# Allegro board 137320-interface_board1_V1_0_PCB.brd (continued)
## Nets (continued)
N2333053: C28.2 L5.1 U5.6(SW)
N2333454: D8.3 U5.3(EN/UVLO) U5.4(VIN)
N2334537: D6.1(ATHODE) R13.2
N2343328: J4.34
N2348416: D13.3 R32.2 R35.2 U6.14(PA0/ADC1_IN1)
N2348424: D14.3 R30.2 R31.2 U6.11(PC3/ADC12_IN9)
N2355333: Q1.1(GATE) R42.1 U6.57(PB5)
N2356046: Q2.1(GATE) R43.1 U6.58(PB6/I2C1_SCL/UART1_TX)
N2358793: J8.2(B1) R48.1 U8.6(AIN3/REFN1)
N2358897: C50.1 FB4.2 U8.12(AVDD)
N2359035: C47.1 C48.2 R50.2 U8.9(REFP0)
N2359039: C48.1 C49.1 R52.2 U8.8(REFN0)
N2359131: J8.1(A1) R47.1 R50.1 R51.1
N2359257: C42.1 C43.2 R47.2 U8.11(AIN0/REFP1)
N2359261: C43.1 C46.1 R48.2 U8.10(AIN1)
N2361697: C53.1 C54.1 FB5.2 U9.10(AVIN) U9.11(PVIN1) U9.12(PVIN2) U9.13(EN)
N2361859: C55.1 U9.9(SS/TR)
N2361891: L6.1 U9.1(SW1) U9.2(SW2) U9.3(SW3)
N2362117: R53.1 U9.4(PG)
N2363053: C56.2 D18.1 L7.1 U10.3(SW)
N2363081: C56.1 U10.2(BOOST)
N2363123: R56.2 R58.1 U10.8(FB)
N2363179: R57.1 U10.10(RT)
N2363207: C58.1 R55.2
N2363211: R55.1 U10.9(VC)
N2363241: C57.1 FB6.2 R54.1 U10.4(VIN)
N2363393: C59.2 R54.2 U10.5(RUN/SS)
N2364151: J1.43
N2365789: R151.1 U43.5(OC2_N) U43.8(OC1_N)
N2365809: R152.1 R153.2 U43.3(EN1_N) U43.4(EN2_N)
N2368555: R154.1 U45.5(OC2_N) U45.8(OC1_N)
N2368583: R155.1 R156.2 U45.3(EN1_N) U45.4(EN2_N)
N2372492: C194.2 U41.4(C1-)
N2372496: C194.1 U41.2(C1+)
N2372506: C197.1 U41.3(V+)
N2372514: C196.1 U41.7(V-)
N2372518: C195.2 U41.6(C2-)
N2372530: C195.1 U41.5(C2+)
N2372534: R143.2 U41.12(FORCEON)
N2372542: R144.2 U41.16(F\O\R\C\E\O\F\F\)
N2372558: R146.1 U41.1(E\N\)
N2372642: R145.2 U41.9(R_OUT)
N2373113: C199.2 U42.4(C1-)
N2373117: C199.1 U42.2(C1+)
N2373127: C202.1 U42.3(V+)
N2373135: C201.1 U42.7(V-)
N2373139: C200.2 U42.6(C2-)
N2373151: C200.1 U42.5(C2+)
N2373155: R148.2 U42.12(FORCEON)
N2373163: R147.2 U42.16(F\O\R\C\E\O\F\F\)
N2373179: R150.1 U42.1(E\N\)
N2373263: R149.2 U42.9(R_OUT)
N2407837: R123.2 U33.4(RXD)
N2407841: R125.1 U33.5(/RE)
N2408507: R126.2 U34.4(RXD)
N2408511: R127.1 U34.5(/RE)
N2410769: R128.2 U35.4(RXD)
N2410773: R130.1 U35.5(/RE)
N2411439: R131.2 U36.4(RXD)
N2411443: R132.1 U36.5(/RE)
N2413701: R133.2 U37.4(RXD)
N2413705: R135.1 U37.5(/RE)
N2414371: R136.2 U38.4(RXD)
N2414375: R137.1 U38.5(/RE)
N2416633: R138.2 U39.4(RXD)
N2416637: R140.1 U39.5(/RE)
N2417303: R141.2 U40.4(RXD)
N2417307: R142.1 U40.5(/RE)
N2487119: R175.1 R208.1 U49.12(A) U50.12(A)
N2487163: R210.1 U49.10(Z) U50.10(Z)
N2487167: R175.2 R209.1 U49.11(B) U50.11(B)
N2487191: R211.1 U49.9(Y) U50.9(Y)
N2496895: C217.2 U51.4(C1-)
N2496899: C217.1 U51.2(C1+)
N2496903: C215.1 U51.7(V-)
N2496907: C219.1 U51.3(V+)
N2496915: Q4.3(DRAIN) Q6.3(DRAIN) R188.1 U51.11(T_IN)
N2496923: C218.2 U51.6(C2-)
N2496931: C218.1 U51.5(C2+)
N2496939: R178.2 U51.12(FORCEON)
N2496947: R179.2 U51.16(F\O\R\C\E\O\F\F\)
N2496959: R177.1 U51.1(E\N\)
N2497023: R180.2 U51.9(R_OUT)
N2498167: R180.1 R185.2 R186.2
N2498410: Q3.3(DRAIN) Q4.1(GATE) R187.1
N2499294: Q5.3(DRAIN) Q6.1(GATE) R189.1
N2500054: R193.1 U51.13(T_OUT)
N2500096: R194.1 U51.8(R_IN)
N2500172: Q7.3(DRAIN) Q8.1(GATE) R195.1
N2500268: Q9.3(DRAIN) Q10.1(GATE) R197.1
N2500326: Q8.3(DRAIN) Q10.3(DRAIN) R196.1 U52.11(T_IN)
N2500498: R200.1 U52.13(T_OUT)
N2500522: R201.1 U52.8(R_IN)
N2500778: C222.2 U52.4(C1-)
N2500782: C224.1 U52.3(V+)
N2500790: C220.1 U52.7(V-)
N2500794: C222.1 U52.2(C1+)
N2500802: C223.2 U52.6(C2-)
N2500814: R203.2 U52.12(FORCEON)
N2500826: C223.1 U52.5(C2+)
N2500830: R202.1 U52.1(E\N\)
N2500842: R204.2 U52.16(F\O\R\C\E\O\F\F\)
N2500874: R205.2 U52.9(R_OUT)
N2500938: R205.1 R206.2 R207.2
N21751111: D15.1(ATHODE) R41.2
N21777191: R61.2 U11.2(R)
N21777192: R59.1 U11.3(RE_N)
N23783590: R63.1 U12.3(RE_N)
N23783591: R64.2 U12.2(RO)
N23815910: R44.1 U7.3(RE_N)
N23815911: R46.2 U7.2(RO)
N23839151: R68.2 U13.2(R)
N23839152: R65.1 U13.3(RE_N)
N23839610: R69.1 U14.3(RE_N)
N23840811: R70.2 U14.2(RO)
N23858251: R74.2 U15.2(R)
N23858252: R71.1 U15.3(RE_N)
N23858410: R75.1 U16.3(RE_N)
N23859371: R76.2 U16.2(RO)
N23877351: R79.2 U17.2(R)
N23877352: R77.1 U17.3(RE_N)
N23877510: R81.1 U18.3(RE_N)
N23878471: R82.2 U18.2(RO)
N23893201: R84.2 U19.2(R)
N23893202: R83.1 U19.3(RE_N)
N23893360: R87.1 U20.3(RE_N)
N23894321: R88.2 U20.2(RO)
N23909051: R90.2 U21.2(R)
N23909052: R89.1 U21.3(RE_N)
N23909210: R93.1 U22.3(RE_N)
N23910171: R94.2 U22.2(RO)
N23924901: R98.2 U23.2(R)
N23924902: R95.1 U23.3(RE_N)
N23925060: R99.1 U24.3(RE_N)
N23926021: R100.2 U24.2(RO)
N23940751: R104.2 U25.2(R)
N23940752: R101.1 U25.3(RE_N)
N23940910: R105.1 U26.3(RE_N)
N23941871: R106.2 U26.2(RO)
N23956601: R108.2 U27.2(R)
N23956602: R107.1 U27.3(RE_N)
N23956760: R111.1 U28.3(RE_N)
N23957721: R112.2 U28.2(RO)
N24852551: R169.2 U47.2(R)
N24852552: R167.1 U47.3(RE_N)
N24852710: R166.1 U48.3(RE_N)
N24853671: R168.2 U48.2(RO)
N24867031: R174.2 U49.2(R)
N24867032: R172.1 U49.3(RE_N)
N24867190: R171.1 U50.3(RE_N)
N24868151: R173.2 U50.2(RO)

Pads without a net: H1 1; H2 1; H3 1; H4 1; H5 1; H6 1; J1 22 63 64; J2 11 26 45 46; J9 3; NOREF#7 1; NOREF#11 1; NOREF#16 1; NOREF#18 1; NOREF#19 1; NOREF#20 1; SP1 1; SP2 1; SP3 1; SP4 1; SP5 1; SP6 1; SP7 1; SP8 1; U1 10; U3 7; U4 7; U5 9; U6 2 4 16 17 24 29 30 34 35 37 38 39 41 44 45 54 59 61 62; U7 1 8; U8 7 14; U10 7; U11 1 8; U12 1 8; U13 1 8; U14 1 8; U15 1 8; U16 1 8; U17 1 8; U18 1 8; U19 1 8; U20 1 8; U21 1 8; U22 1 8; U23 1 8; U24 1 8; U25 1 8; U26 1 8; U27 1 8; U28 1 8; U41 10; U42 10; U44 4 6; U46 4 6; U47 1 8; U48 1 8; U49 1 8; U50 1 8; U51 10; U52 10

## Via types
v1: diameter 0.559, hole 0.254, TOP to BOTTOM, 1085 vias

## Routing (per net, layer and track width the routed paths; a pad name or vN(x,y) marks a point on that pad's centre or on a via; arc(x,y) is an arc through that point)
GND: length 443.2
  TOP w0.254: U6.63 76.76,48.82 v1(77.09,49.15) ; v1(83.44,37.97) 83.26,37.79 U6.31 ; v1(73.03,40.01) 73.43,40.41 U6.12 ; U41.14 83.99,63.21 v1(84.33,62.87) ; v1(76.96,37.97) 76.76,37.77 U6.18 ; U52.14 102.53,53.43 v1(102.87,53.09) ; U51.14 102.53,37.55 v1(102.87,37.21) ; v1(72.52,46.48) 72.52,45.47 73.07,44.91 U6.3 75.74,44.91 v1(75.82,44.83) ; U42.14 v1(89.19,20.07) ; U6.47 86.94,45.41 v1(87.12,45.59)
  TOP w0.305: U8.4 62.16,20.01 v1(61.85,20.32) 62.19,20.66 U8.3 ; U8.5 62.16,19.36 v1(61.85,19.05)
  TOP w0.381: U19.6 v1(44.45,25.65) ; D24.3 v1(18.03,45.09) ; SW1.4 v1(86.36,25.85) ; C50.2 v1(75.31,19.3) ; C215.2 v1(106.05,28.45) ; C224.2 v1(102.23,44.32) ; v1(102.36,66.42) 102.62,66.67 C27.2 ; Q10.2 v1(109.54,51.18) ; C94.2 v1(48.26,21.08) ; U7.6 v1(139.7,9.91) ; v1(48.26,52.83) C70.2 C69.2 ; v1(119.38,21.08) C213.2 C211.2 ; v1(36.83,9.78) 36.83,9.4 37.47,8.76 R103.2 ; U47.7 v1(116.2,12.83) ; U36.10 v1(124.33,66.67) ; v1(121.16,27.94) 120.78,27.56 C129.2 118.36,27.56 v1(117.98,27.94) ; U25.6 v1(44.45,9.78) ; C162.2 C164.2 v1(117.98,47.62) ; R43.2 v1(79.38,53.21) 79.31,53.27 Q2.2 ; U39.3 v1(124.33,60.96) ; U36.1 v1(124.33,78.11) ; R146.2 v1(72.26,64.77) ; U13.7 v1(45.72,41.53) ; R42.2 v1(80.64,53.21) ; C178.2 C180.2 v1(117.98,62.23) ; U37.3 v1(124.33,46.35) ; J9.6 v1(80.01,76.33) ; v1(81.92,53.21) 81.92,54.13 Q1.2 ; D19.3 v1(18.03,57.78) ; Q6.2 v1(109.54,35.31) ; v1(81.66,31.24) R160.2 R158.2 ; v1(121.16,57.15) 120.78,56.77 118.36,56.77 v1(117.98,57.15) ; C49.2 v1(65.41,12.32) ; D51.3 v1(143.51,39.37) ; C207.2 C209.2 v1(108.58,21.08) ; U36.3 v1(124.33,75.56) ; U11.7 v1(35.56,41.53) ; C155.2 v1(117.98,67.94) ; 122.79,48.9 v1(124.33,48.9) ; R177.2 v1(100.97,28.45) ; v1(72.52,42.93) C31.2 v1(71.12,42.29) v1(69.22,42.29) 67.69,42.29 67.31,42.67 v1(67.31,43.56) v1(67.31,45.85) 67.31,46.74 67.69,47.12 v1(69.22,47.12) v1(71.12,47.12) C30.2 v1(72.52,46.48) ; C55.2 v1(88.52,37.47) ; U21.6 v1(54.61,25.65) ; R19.2 104.9,69.22 v1(105.54,68.58) ; U15.7 v1(55.88,41.53) ; C132.2 C130.2 v1(117.98,33.02) ; v1(36.83,25.65) 36.83,25.02 37.21,24.64 R86.2 ; 27.94,40.51 v1(26.92,40.51) ; R172.2 v1(121.92,6.73) ; R162.2 R164.2 v1(84.2,31.24) ; D12.1 v1(67.56,35.88) ; U39.10 v1(124.33,52.07) ; C85.2 C86.2 v1(27.94,21.08) ; v1(48.26,36.96) C82.2 C81.2 ; C219.2 v1(102.23,28.45) ; D28.3 v1(18.03,36.83) ; 38.1,40.51 37.47,40.51 36.83,41.15 v1(36.83,41.53) ; C14.2 v1(58.93,77.22) ; C58.2 87.38,66.67 v1(87.12,66.42) ; C93.2 v1(49.53,21.08) ; U47.6 v1(114.94,12.83) ; D34.3 v1(18.03,27.3) ; v1(90.3,68.58) 89.66,69.22 R57.2 ; R97.2 v1(27.05,8.76) ; R89.2 v1(50.8,22.73) ; D32.3 v1(18.03,30.48) ; R71.2 v1(50.8,38.61) ; Q7.2 v1(112.72,47.37) ; U36.9 v1(124.33,67.94) ; C197.2 v1(72.26,62.23) ; D9.1 v1(64.01,41.85) ; v1(79.76,25.91) 79.81,25.85 SW1.3 ; D6.2 v1(78.23,25.91) ; Q5.2 v1(109.54,31.5) ; R140.2 v1(117.98,58.42) ; U45.1 v1(97.16,11.68) ; D11.1 v1(67.56,32.71) ; R202.2 v1(100.97,44.32) ; U23.6 v1(34.29,9.78) ; U33.1 v1(124.33,34.29) ; R77.2 v1(30.48,22.73) ; U25.7 v1(45.72,9.78) ; D49.3 v1(15.88,65.41) ; C154.2 v1(117.98,76.83) ; v1(83.19,57.91) 83.19,57.4 D15.2 ; U7.7 v1(140.97,9.91) ; R176.2 117.98,8.76 v1(117.86,8.89) ; U49.7 127,10.29 126.62,9.91 v1(125.73,9.91) U49.6 ; D16.3 v1(144.15,34.29) ; R92.2 47.75,24.64 46.99,25.4 v1(46.99,25.65) ; C73.2 C74.2 v1(27.94,36.96) ; U39.1 v1(124.33,63.5) ; C198.2 v1(89.53,26.16) ; U15.6 v1(54.61,41.53) ; Q9.2 v1(109.54,47.37) ; C196.2 v1(72.26,59.69) ; R165.2 107.82,8.76 107.3,8.24 v1(107.3,6.73) ; R125.2 v1(117.98,29.21) ; U19.7 v1(45.72,25.65) ; U27.7 v1(55.88,9.78) ; C220.2 v1(106.05,44.32) ; U44.2 v1(13.59,69.22) ; U13.6 v1(44.45,41.53) ; v1(117.98,42.55) 118.36,42.16 C161.2 120.78,42.16 v1(121.16,42.55) ; U11.6 v1(34.29,41.53) ; R78.2 v1(27.05,24.64) ; U46.2 v1(146.43,30.48) ; C179.2 v1(117.98,53.34) ; D26.3 v1(18.03,41.91) ; R110.2 47.75,8.76 46.99,9.53 v1(46.99,9.78) ; D20.3 v1(18.03,54.61) ; R132.2 v1(117.98,73.03) ; U23.7 v1(35.56,9.78) ; D50.3 v1(144.15,23.5) ; U17.6 v1(34.29,25.65) ; v1(27.94,52.83) C62.2 C61.2 ; C156.2 v1(117.98,75.56) ; D54.3 v1(143.51,52.07) ; U33.3 v1(124.33,31.75) ; U33.9 v1(124.33,24.13) ; U33.10 v1(124.33,22.86) ; R83.2 v1(40.64,22.73) ; U39.9 v1(124.33,53.34) ; R59.2 v1(30.48,38.61) ; U17.7 v1(35.56,25.65) ; Q8.2 v1(112.72,51.18) ; R95.2 v1(30.48,6.86) ; v1(121.16,71.75) 120.78,71.37 C153.2 118.36,71.37 v1(117.98,71.75) ; 48.26,40.51 47.62,40.51 46.99,41.15 v1(46.99,41.53) ; R65.2 v1(40.64,38.61) ; C89.2 C90.2 v1(38.1,21.08) ; U37.10 v1(124.33,37.47) ; C65.2 C66.2 v1(38.1,52.83) ; C20.1 v1(36.2,62.99) ; U27.6 v1(54.61,9.78) ; R135.2 v1(117.98,43.81) ; C163.2 v1(117.98,38.73) ; R101.2 v1(40.64,6.86) ; D30.3 v1(18.03,33.66) ; R38.2 v1(78.11,53.21) ; D22.3 v1(18.03,51.44) ; D17.3 v1(144.15,26.67) ; D36.3 v1(18.03,24.13) ; U21.7 v1(55.88,25.65) ; U37.9 v1(124.33,38.73) ; R23.2 v1(64.14,61.47) ; D14.1 v1(64.01,38.67) ; v1(38.1,36.96) C78.2 C77.2 ; v1(75.31,16.76) C46.2 C42.2 ; C131.2 v1(117.98,24.13) ; R107.2 v1(50.8,6.86) ; D3.2 v1(78.23,27.43) ; Q4.2 v1(112.72,35.31) ; Q3.2 v1(112.72,31.5) ; C47.2 v1(66.67,12.32) ; U43.1 v1(53.34,57.4) ; R167.2 v1(111.12,6.73)
  BOTTOM w0.254: U4.6 102.89,66.95 v1(102.36,66.42) ; U3.6 37.74,65.64 v1(38.1,65.28) ; v1(67.31,62.48) 67.67,62.85 U5.5 ; v1(90.3,67.31) 89.93,66.95 U10.6 87.65,66.95 v1(87.12,66.42)
  BOTTOM w0.381: R153.1 v1(55.88,60.33) ; C87.2 C88.2 v1(27.94,6.86) ; 122.79,48.9 v1(124.33,48.9) ; C9.2 v1(45.09,82.04) ; C204.2 v1(54.61,60.33) ; C75.2 C76.2 v1(27.94,22.73) ; R171.2 v1(121.92,21.08) ; C45.2 C44.2 v1(133.35,14.22) ; R75.2 v1(50.8,52.83) ; C34.2 v1(78.87,40.01) ; U38.3 v1(124.33,40.01) ; R27.1 v1(68.83,40.01) ; U22.7 v1(55.88,31.11) ; C51.2 v1(67.56,20.32) ; v1(27.94,38.61) C64.2 C63.2 ; R8.2 v1(41.27,82.04) ; U48.7 v1(116.2,18.03) ; C40.2 75.69,44.96 v1(75.82,44.83) ; R58.2 89.92,70.48 ; R30.1 v1(68.83,38.73) ; U24.7 v1(35.56,15.24) ; C32.2 86.16,25.85 v1(86.36,25.85) ; C35.2 v1(78.87,41.27) ; R156.1 C206.2 v1(98.42,14.61) ; U28.6 v1(54.61,18.16) ; D52.3 v1(143.51,42.55) ; U16.6 v1(54.61,49.91) ; C202.2 v1(90.17,16.89) ; v1(38.1,6.86) C92.2 C91.2 ; U1.8 v1(43.56,76.2) ; U35.9 v1(124.33,76.83) ; C155.2 v1(117.98,67.94) ; R63.2 v1(30.48,52.83) ; U37.10 v1(124.33,37.47) ; v1(80.39,37.97) 80.52,37.85 C41.2 ; U33.10 v1(124.33,22.86) ; D28.3 v1(18.03,36.83) ; U50.6 v1(125.73,18.03) 126.62,18.03 127,17.65 U50.7 ; v1(121.16,43.81) 120.78,44.2 C169.2 118.36,44.2 v1(117.98,43.81) ; C179.2 v1(117.98,53.34) ; U18.7 v1(35.56,31.11) ; v1(117.98,58.42) 118.36,58.8 C185.2 120.78,58.8 v1(121.16,58.42) ; C80.2 C79.2 v1(38.1,22.73) ; C37.2 v1(83.44,37.97) ; C22.2 v1(41.27,68.45) ; R93.2 v1(50.8,36.96) ; C163.2 v1(117.98,38.73) ; U35.3 v1(124.33,69.22) ; R24.1 v1(68.83,41.27) ; U28.7 v1(55.88,15.24) ; v1(121.16,29.21) 120.78,29.59 C138.2 118.36,29.59 v1(117.98,29.21) ; U34.9 v1(124.33,33.02) ; R51.2 v1(72.52,19.3) ; v1(117.98,73.03) 118.36,73.41 C145.2 120.78,73.41 v1(121.16,73.03) ; R87.2 v1(40.64,36.96) ; U14.6 v1(44.45,49.91) ; v1(109.86,6.73) C208.2 C210.2 ; U20.6 v1(44.45,34.04) ; R20.2 105.16,70.48 ; U38.9 v1(124.33,47.62) ; C36.2 v1(78.87,42.55) ; C8.2 v1(42.55,79.25) ; D10.1 v1(64.01,41.85) ; C10.2 v1(36.7,77.6) ; C148.2 v1(117.98,66.67) ; C38.2 v1(87.12,45.59) ; v1(48.26,22.73) C84.2 C83.2 ; C131.2 v1(117.98,24.13) ; U36.10 v1(124.33,66.67) ; C164.2 v1(117.98,47.62) ; R14.2 v1(42.55,71.25) ; C186.2 v1(117.98,52.07) ; U34.3 v1(124.33,25.4) ; C72.2 C71.2 v1(48.26,38.61) ; R99.2 v1(30.48,21.08) ; C130.2 v1(117.98,33.02) ; C214.2 C212.2 v1(120.65,6.73) ; R105.2 v1(40.64,21.08) ; R35.1 v1(68.83,37.47) ; D53.3 v1(143.51,55.24) ; R1.1 v1(36.7,80.14) ; C67.2 C68.2 v1(38.1,38.61) ; R150.2 v1(87.63,16.89) ; U18.6 v1(34.29,34.04) ; R69.2 v1(40.64,52.83) ; R81.2 v1(30.48,36.96) ; U36.1 v1(124.33,78.11) ; U39.1 v1(124.33,63.5) ; v1(77.09,49.15) 76.96,49.02 C39.2 ; U14.7 v1(45.72,46.99) ; C95.2 v1(48.26,6.86) ; R2.1 v1(117.98,78.11) ; D20.3 v1(18.03,54.61) ; R130.2 v1(117.98,71.75) ; U24.6 v1(34.29,18.16) ; U40.3 v1(124.33,54.61) ; C49.2 v1(65.41,12.32) ; U39.10 v1(124.33,52.07) ; C154.2 v1(117.98,76.83) ; R15.2 v1(37.47,71.25) ; C216.2 102.74,37.34 v1(102.87,37.21) ; U33.1 v1(124.33,34.29) ; C139.2 v1(117.98,22.86) ; U22.6 v1(54.61,34.04) ; U20.7 v1(45.72,31.11) ; C180.2 v1(117.98,62.23) ; R142.2 v1(117.98,57.15) ; D32.3 v1(18.03,30.48) ; U26.6 v1(44.45,18.16) ; R111.2 v1(50.8,21.08) ; U16.7 v1(55.88,46.99) ; C59.1 v1(91.31,65.41) ; C201.2 v1(92.71,16.89) ; R49.2 v1(137.16,12.83) ; U40.9 v1(124.33,62.23) ; D30.3 v1(18.03,33.66) ; C25.1 v1(106.55,65.41) ; R127.2 v1(117.98,27.94) ; U48.6 v1(114.94,18.03) ; C33.2 v1(76.96,37.97) ; C193.2 v1(84.33,62.87) ; C96.2 v1(49.53,6.86) ; C172.2 v1(117.98,37.47) ; R137.2 v1(117.98,42.55) ; C221.2 102.74,53.21 v1(102.87,53.09) ; U26.7 v1(45.72,15.24) ; R44.2 v1(135.89,12.83) ; R166.2 v1(111.12,21.08) ; D22.3 v1(18.03,51.44) ; D36.3 v1(18.03,24.13) ; D25.3 v1(18.03,48.26) ; U12.6 v1(34.29,49.91) ; U12.7 v1(35.56,46.99) ; R7.2 v1(36.7,78.87) ; D13.1 v1(64.01,38.67) ; D26.3 v1(18.03,41.91)
  vias: v1(19.68,71.12) v1(20.95,66.29) v1(20.95,65.02) v1(21.21,79.76) v1(21.21,78.49) v1(22.23,66.29) v1(22.23,65.02) v1(22.48,79.76) v1(22.48,78.49) v1(25.91,81.03) v1(25.91,79.76) v1(25.91,66.93) v1(25.91,65.66) v1(27.18,81.03) v1(27.18,79.76) v1(27.18,66.93) v1(27.18,65.66) v1(30.99,81.03) v1(30.99,79.76) v1(30.99,66.93) v1(30.99,65.66) v1(32.26,81.03) v1(32.26,79.76) v1(32.26,66.93) v1(32.26,65.66) v1(38.1,64.26) v1(38.73,64.77) v1(39.37,65.28) v1(39.37,64.26) v1(41.53,77.34) v1(41.53,76.2) v1(41.53,75.06) v1(41.78,56.01) v1(41.78,54.74) v1(42.55,77.34) v1(42.55,76.2) v1(42.55,75.06) v1(43.05,56.01) v1(43.05,54.74) v1(43.56,77.34) v1(43.56,75.06) v1(44.32,68.33) v1(44.32,67.06) v1(45.59,68.33) v1(45.59,67.06) v1(49.53,73.91) v1(50.8,73.91) v1(52.07,73.91) v1(53.34,73.91) v1(60.45,67.82) v1(60.45,64.26) v1(61.72,67.82) v1(61.72,64.26) v1(63.83,77.14) v1(63.83,76.02) v1(64.39,76.58) v1(64.95,77.14) v1(64.95,76.02) v1(66.04,62.48) v1(66.04,61.47) v1(66.67,61.98) v1(67.31,61.47) v1(67.69,50.16) v1(67.69,48.9) v1(68.96,50.16) v1(68.96,48.9) v1(91.31,68.58) v1(91.31,67.31) v1(93.42,37.39) v1(93.42,36.27) v1(94.54,37.39) v1(94.54,36.27) v1(99.69,66.04) v1(99.69,64.77) v1(100.97,66.04) v1(100.97,64.77) v1(103.5,10.67) v1(104.78,10.67) v1(105.54,67.31) v1(106.05,10.67) v1(106.55,68.58) v1(106.55,67.31) v1(114.94,66.04) v1(114.94,64.77) v1(116.2,66.04) v1(116.2,64.77)
GND_ISO12: length 59
  TOP w0.381: D42.3 v1(145.67,42.55) ; U33.16 v1(130.94,29.21) ; U33.11 v1(130.94,22.86) ; v1(137.29,33.02) 136.78,32.51 136.27,32.51 C133.2 136.27,31.75 v1(137.29,31.75) ; C134.2 v1(137.29,25.4) ; U33.14 v1(130.94,26.67) ; U33.20 v1(130.94,34.29) ; C135.2 v1(137.29,24.13)
  ART04 w0.381: v1(145.67,39.37) v1(145.67,42.55) ; v1(145.67,39.37) 140.59,34.29 v1(137.29,34.29) v1(137.29,33.02) ; v1(145.67,39.37) 146.26,38.78 150.66,38.78 151.36,39.47 151.36,48.94 J2.21
  BOTTOM w0.381: U34.14 v1(130.94,30.48) ; v1(137.29,30.48) 136.78,29.97 136.27,29.97 C141.2 136.27,29.21 v1(137.29,29.21) ; D41.3 v1(145.67,39.37) ; C135.2 v1(137.29,24.13) ; C136.2 v1(137.29,34.29) ; C142.2 v1(137.29,33.02) ; U33.20 v1(130.94,34.29) ; C143.2 v1(137.29,22.86) ; U34.16 v1(130.94,27.94) ; U33.11 v1(130.94,22.86)
GND_ISO13: length 52.9
  TOP w0.381: C160.2 v1(137.29,69.22) ; v1(137.29,76.83) 136.78,76.33 136.27,76.33 C157.2 136.27,75.56 v1(137.29,75.56) ; U36.11 v1(130.94,66.67) ; C159.2 v1(137.29,67.94) ; D44.3 v1(145.67,61.59) ; U36.16 v1(130.94,73.03) ; U36.14 v1(130.94,70.48) ; U36.20 v1(130.94,78.11)
  ART03 w0.381: v1(145.67,61.59) 145.71,61.64 J2.16
  ART04 w0.381: v1(137.29,74.3) v1(137.29,73.03) 145.67,64.64 v1(145.67,61.59) v1(145.67,58.42)
  BOTTOM w0.381: C158.2 v1(137.29,78.11) ; C152.2 v1(137.29,76.83) ; U36.20 v1(130.94,78.11) ; U35.14 v1(130.94,74.3) ; U35.16 v1(130.94,71.75) ; v1(137.29,74.3) 136.78,73.79 136.27,73.79 C149.2 136.27,73.03 v1(137.29,73.03) ; U36.11 v1(130.94,66.67) ; D43.3 v1(145.67,58.42) ; C159.2 v1(137.29,67.94) ; C151.2 v1(137.29,66.67)
GND_ISO14: length 52.4
  TOP w0.381: C167.2 v1(137.29,38.73) ; v1(137.29,46.35) 136.27,46.35 C165.2 136.27,47.12 136.78,47.12 v1(137.29,47.62) ; D46.3 v1(145.67,48.9) ; 132.48,48.9 v1(130.94,48.9) ; U37.11 v1(130.94,37.47) ; C168.2 v1(137.29,40.01) ; U37.16 v1(130.94,43.81) ; U37.14 v1(130.94,41.27)
  ART04 w0.381: v1(137.29,47.62) v1(137.29,48.9) 138.87,50.48 144.08,50.48 v1(145.67,48.9) ; v1(145.67,48.9) v1(145.67,45.72) ; v1(145.67,48.9) 146.98,50.21 150.78,50.21 151.93,51.35 153.32,51.35 155.17,49.51 J2.36
  BOTTOM w0.381: U38.16 v1(130.94,42.55) ; C175.2 v1(137.29,37.47) ; 132.48,48.9 v1(130.94,48.9) ; C166.2 v1(137.29,48.9) ; U38.14 v1(130.94,45.09) ; C167.2 v1(137.29,38.73) ; v1(137.29,45.09) 136.78,44.58 136.27,44.58 C173.2 136.27,43.81 v1(137.29,43.81) ; C176.2 v1(137.29,47.62) ; D45.3 v1(145.67,45.72) ; U37.11 v1(130.94,37.47)
GND_ISO15: length 53.1
  TOP w0.381: U39.11 v1(130.94,52.07) ; C183.2 v1(137.29,53.34) ; U39.20 v1(130.94,63.5) ; U39.14 v1(130.94,55.88) ; v1(137.29,60.96) 136.27,60.96 C181.2 136.27,61.72 136.78,61.72 v1(137.29,62.23) ; D48.3 v1(145.67,55.24) ; U39.16 v1(130.94,58.42) ; C184.2 v1(137.29,54.61)
  ART04 w0.381: v1(137.29,54.61) v1(137.29,53.34) 138.56,53.34 138.87,53.66 144.08,53.66 v1(145.67,52.07) 146.3,52.7 146.3,54.61 v1(145.67,55.24) 145.67,56.39 148.63,59.35 150.78,59.35 151.93,60.49 J2.31
  BOTTOM w0.381: v1(137.29,58.42) 136.27,58.42 C189.2 136.27,59.18 136.78,59.18 v1(137.29,59.69) ; C183.2 v1(137.29,53.34) ; U40.14 v1(130.94,59.69) ; U39.11 v1(130.94,52.07) ; C191.2 v1(137.29,52.07) ; C192.2 v1(137.29,62.23) ; C182.2 v1(137.29,63.5) ; U40.16 v1(130.94,57.15) ; D47.3 v1(145.67,52.07) ; U39.20 v1(130.94,63.5)
VCC_MAIN: length 82.2
  TOP w0.381: U15.14 v1(48.26,49.91) C70.1 ; C78.1 v1(38.1,34.04) U19.14 ; R6.1 v1(72.39,27.43) ; U11.13 v1(29.21,49.91) C61.1 ; C211.1 v1(120.65,18.03) U49.13 ; C93.1 v1(49.53,18.16) U27.13 ; C65.1 v1(39.37,49.91) U13.13 ; C90.1 v1(38.1,18.16) U25.14 ; v1(61.21,35.56) 65.66,35.56 66.8,36.7 69.34,36.7 69.72,37.08 R32.1 ; U17.13 v1(29.21,34.04) C73.1 ; U15.13 v1(49.53,49.91) C69.1 ; C213.1 v1(119.38,18.03) U49.14 ; C66.1 v1(38.1,49.91) U13.14 ; U43.2 v1(54.61,57.4) ; U19.13 v1(39.37,34.04) C77.1 ; C81.1 v1(49.53,34.04) U21.13 ; C89.1 v1(39.37,18.16) U25.13 ; U21.14 v1(48.26,34.04) C82.1 ; R151.2 v1(57.15,69.09) ; U11.14 v1(27.94,49.91) C62.1 ; v1(40.01,82.04) 41.02,81.03 v1(49.53,81.03) ; C85.1 v1(29.21,18.16) U23.13 ; U27.14 v1(48.26,18.16) C94.1 ; U17.14 v1(27.94,34.04) C74.1 ; C209.1 v1(108.58,18.03) U47.14 ; U23.14 v1(27.94,18.16) C86.1 ; 109.86,16.64 v1(109.86,18.03) C207.1
  BOTTOM w0.381: C204.1 v1(54.61,57.4) ; R5.1 v1(40.01,82.04) ; v1(72.39,27.43) 72.39,28.7
  vias: v1(49.53,79.76) v1(50.8,81.03) v1(50.8,79.76) v1(57.15,73.41) v1(57.15,72.14) v1(58.42,73.41) v1(58.42,72.14) v1(59.94,29.72) v1(59.94,28.45) v1(61.21,29.72) v1(61.21,28.45) v1(86.61,33.78) v1(86.61,32.51) v1(87.88,33.78) v1(87.88,32.51) v1(99.31,22.86) v1(99.31,21.59) v1(100.58,22.86) v1(100.58,21.59)
VCC_SPARE: length 63.9
  TOP w0.381: R26.1 69.09,39.37 68.2,39.37 v1(67.56,40.01) ; v1(49.02,65.28) 48.01,66.29 42.29,66.29 38.73,69.85 v1(38.73,71.25) ; R13.1 v1(72.39,25.91) ; U45.2 v1(98.42,11.68)
  ART04 w0.381: v1(98.42,11.68) 97.16,12.95 v1(97.16,17.02)
  BOTTOM w0.254: 40.64,62.23 40.35,61.94 39.91,61.94 39.73,62.12 U3.1
  BOTTOM w0.381: v1(98.42,11.68) C206.1 ; 40.64,62.23 41.78,63.37 47.12,63.37 ; v1(97.16,17.02) R154.2 87.25,17.91 81.53,23.62 74.68,23.62 v1(72.39,25.91) ; R12.1 v1(38.73,71.25)
  vias: v1(49.02,64.01) v1(50.29,65.28) v1(50.29,64.01) v1(72.26,56.01) v1(72.26,54.74) v1(73.53,56.01) v1(73.53,54.74) v1(99.69,63.5) v1(99.69,62.23) v1(100.97,63.5) v1(100.97,62.23) v1(114.94,63.5) v1(114.94,62.23) v1(116.2,63.5) v1(116.2,62.23)
VDD33_MAIN: length 83.1
  TOP w0.254: v1(63.88,74.04) 64.14,74.3 U2.14 ; U41.15 84.05,63.86 v1(84.33,64.14) ; U6.15 73.41,38.91 73.15,38.66 73.15,37.97
  TOP w0.381: v1(72.39,35.56) 73.15,36.32 73.15,37.97 ; R9.2 v1(69.72,78.11)
  TOP w0.508: v1(84.33,60.96) v1(85.6,60.96)
  TOP w0.762: v1(85.6,60.96) 85.6,57.78 92.9,50.48 D55.2
  ART04 w0.762: v1(68.07,70.99) v1(69.34,70.99) 73.66,66.67 73.66,58.55 74.8,57.4 74.8,41.27 74.04,40.51 74.04,37.21 v1(72.39,35.56) v1(72.39,34.29)
  BOTTOM w0.381: v1(63.88,74.04) 68.33,74.04 C11.1 ; v1(69.72,78.11) 70.23,78.11 70.74,77.6 70.74,72.64 70.36,72.26 v1(69.34,72.26) ; R144.1 v1(84.33,64.14) ; v1(84.33,60.96) 84.07,60.96 R143.1 ; C193.1 v1(81.53,62.87)
  vias: v1(68.07,72.26)
VDD33_MAIN_485: length 58.1
  TOP w0.254: v1(93.47,34.29) 93.73,34.55 U9.14
  TOP w0.381: v1(117.98,25.4) 118.36,25.78 120.78,25.78 v1(121.16,25.4) ; U39.8 v1(121.16,54.61) ; v1(121.16,54.61) 120.78,54.99 C177.1 118.36,54.99 v1(117.98,54.61) ; v1(121.16,54.61) C179.1 ; v1(117.98,40.01) 118.36,40.39 C161.1 120.78,40.39 v1(121.16,40.01) ; C132.1 C130.1 v1(121.28,33.02) U33.2 ; R53.2 99.19,38.48 99.95,37.72 99.95,32.77 99.69,32.51 v1(98.93,32.51) ; C162.1 C164.1 v1(121.28,47.62) U37.2 ; U37.8 v1(121.16,40.01) ; v1(121.16,40.01) C163.1 ; U39.2 v1(121.28,62.23) C180.1 C178.1 ; U33.8 v1(121.16,25.4) ; v1(121.16,25.4) C131.1
  BOTTOM w0.381: U35.8 v1(121.28,75.56) ; v1(121.28,75.56) 120.9,75.18 C145.1 ; v1(121.28,75.56) 120.02,76.83 C147.1 ; v1(97.66,32.51) 95.25,32.51 v1(93.47,34.29) ; v1(121.16,66.67) C148.1 C146.1 v1(121.16,67.94) U35.2
  vias: v1(97.66,31.24) v1(98.93,31.24) v1(114.43,25.4) v1(114.43,24.13) v1(115.7,25.4) v1(115.7,24.13)
VDD33_RS232: length 18.6
  TOP w0.254: U52.15 101.88,53.37 v1(101.6,53.09) ; v1(101.6,37.21) 101.88,37.49 U51.15
  TOP w0.381: R178.1 v1(104.78,42.67) ; R203.1 v1(104.78,58.55) ; R204.1 v1(99.69,58.55) ; R179.1 v1(99.69,42.67)
  BOTTOM w0.381: R190.1 112.27,33.21 v1(112.72,33.66) ; R178.1 v1(104.78,42.67) ; v1(101.6,37.21) 101.73,37.34 C216.1 ; R199.1 109.09,49.08 v1(109.54,49.53) ; v1(109.54,33.66) 109.09,33.21 R191.1 ; v1(112.72,53.34) 112.27,52.89 R195.2 ; R189.2 109.09,37.02 v1(109.54,37.47) ; v1(112.72,49.53) 112.27,49.08 R198.1 ; R203.1 v1(104.78,58.55) ; R187.2 112.27,37.02 v1(112.72,37.47) ; v1(101.6,53.09) 101.73,53.21 C221.1 ; v1(109.54,53.34) 109.09,52.89 R197.2
  vias: v1(99.31,52.07) v1(99.31,50.8) v1(100.58,52.07) v1(100.58,50.8)
VDD33_SPARE: length 49.8
  TOP w0.254: U42.15 v1(88.54,22.61) ; U6.10 75.93,41.41 v1(76.07,41.27)
  TOP w0.381: R147.1 v1(88.27,26.16) ; C198.1 89.53,23.6 v1(88.54,22.61) ; R148.1 v1(90.81,26.16)
  TOP w0.762: 72.39,31.11 73.91,29.59 86.87,29.59 v1(88.27,28.19) v1(89.53,28.19)
  ART04 w0.508: v1(72.39,32.38) 75.06,35.05 75.06,40.26 v1(76.07,41.27)
  BOTTOM w0.254: 109,69.51 109,69.12 108.82,68.94 U4.1
  BOTTOM w0.381: R18.1 104.39,75.95 104.78,76.33 C26.1 ; 109,69.51 107.44,71.07 107.44,75.82
  vias: v1(95,53.59) v1(95,52.32) v1(96.27,53.59) v1(105.54,78.87) v1(105.54,77.6) v1(106.81,78.87) v1(106.81,77.6)
VDD33_SPARE_485: length 103.4
  TOP w0.381: v1(121.16,69.22) 120.78,69.6 C153.1 118.36,69.6 v1(117.98,69.22) ; v1(121.16,69.22) C155.1 ; v1(121.16,69.22) U36.8 ; C156.1 C154.1 v1(121.28,76.83) U36.2
  BOTTOM w0.254: 93.76,69.51 93.76,69.12 93.58,68.94 U10.1
  BOTTOM w0.381: U12.14 v1(27.94,41.53) 27.94,40.51 ; U34.8 v1(121.28,31.75) ; v1(121.28,31.75) 120.02,33.02 C140.1 ; v1(121.28,31.75) 120.9,31.37 C138.1 118.36,31.37 v1(117.98,31.75) ; U24.14 v1(27.94,9.78) C88.1 ; C210.1 v1(108.58,9.91) U48.14 ; C75.1 v1(29.21,25.65) ; C83.1 v1(49.53,25.65) ; 29.21,40.51 v1(29.21,41.53) ; U28.14 v1(48.26,9.78) C95.1 ; R56.1 89.15,75.95 89.53,76.33 C60.1 ; C208.1 v1(109.86,9.91) ; U14.14 v1(38.1,41.53) 38.1,40.51 ; C170.1 120.02,47.62 v1(121.28,46.35) ; v1(117.98,60.96) 118.36,60.58 C185.1 120.9,60.58 v1(121.28,60.96) ; v1(121.28,46.35) 120.9,45.97 C169.1 118.36,45.97 v1(117.98,46.35) ; v1(121.28,46.35) U38.8 ; C80.1 v1(39.37,25.65) ; U16.14 v1(48.26,41.53) 48.26,40.51 ; 39.37,40.51 v1(39.37,41.53) ; U26.14 v1(38.1,9.78) C92.1 ; 93.76,69.51 92.2,71.07 92.2,75.82 ; U50.14 v1(119.38,9.91) C214.1 ; U38.2 v1(121.16,38.73) C171.1 C172.1 v1(121.16,37.47) ; v1(121.28,60.96) 120.02,62.23 C187.1 ; v1(121.28,60.96) U40.8 ; C84.1 v1(48.26,25.65) U22.14 ; v1(121.16,22.86) C139.1 C137.1 v1(121.16,24.13) U34.2 ; C91.1 v1(39.37,9.78) ; C79.1 v1(38.1,25.65) U20.14 ; C76.1 v1(27.94,25.65) U18.14 ; C212.1 v1(120.65,9.91) ; C87.1 v1(29.21,9.78) ; v1(121.16,52.07) C186.1 C188.1 v1(121.16,53.34) U40.2 ; 49.53,40.51 v1(49.53,41.53) ; C96.1 v1(49.53,9.78)
  BOTTOM w0.508: v1(120.65,9.91) v1(119.38,9.91)
  vias: v1(46.61,12.45) v1(46.61,11.43) v1(47.37,12.45) v1(47.37,11.43) v1(90.3,78.87) v1(90.3,77.6) v1(91.57,78.87) v1(91.57,77.6) v1(97.16,10.67) v1(98.42,10.67) v1(99.69,10.67) v1(100.97,10.67) v1(117.86,81.15) v1(117.86,80.14) v1(118.75,81.15) v1(118.75,80.14)
VDD33_SWITCH: length 100.7
  TOP w0.254: v1(84.2,45.59) 84.52,45.91 U6.48 ; v1(83.44,35.18) 83.76,35.5 U6.32 ; v1(75.82,46.1) 75.63,45.91 U6.1 ; v1(76.96,35.18) 77.26,35.48 U6.19 ; v1(75.82,49.15) 76.26,48.71 U6.64
  TOP w0.305: v1(70.36,20.32) 70.05,20.01 68.96,20.01
  TOP w0.381: D11.2 v1(67.56,30.79) ; D14.2 v1(64.01,36.76) ; U7.14 v1(133.35,18.03) ; J9.2 v1(74.93,76.33) ; D9.2 v1(64.01,39.94) ; J9.4 v1(77.47,76.33) ; v1(67.56,33.97) D12.2
  ART03 w0.508: v1(134.62,18.03) v1(133.35,18.03) 132.21,19.18 125.09,19.18 122.17,22.1 117.35,22.1 116.59,22.86 v1(101.85,22.86)
  BOTTOM w0.254: U5.8 66.67,58.8 66.55,58.67 66.55,58.04 66.29,57.78 64.77,57.78
  BOTTOM w0.381: v1(79.12,37.97) 78.99,37.85 C41.1 ; C38.1 v1(84.2,45.59) ; v1(82.93,31.24) R161.1 R163.1 ; D10.2 v1(64.01,39.94) ; FB3.2 v1(79.25,43.81) ; C45.1 v1(134.62,18.03) ; R37.1 84.33,39.12 v1(84.2,38.99) ; v1(84.2,40.26) 84.33,40.39 R39.1 ; R159.1 R157.1 v1(80.39,31.24) ; C39.1 75.95,49.02 v1(75.82,49.15) ; v1(75.82,46.1) 75.69,45.97 C40.1 ; v1(83.44,35.18) C37.1 88.65,36.07 v1(101.85,22.86) ; D13.2 v1(64.01,36.76) ; C33.1 v1(76.96,35.18) ; C44.1 v1(133.35,18.03) ; C51.1 v1(70.36,20.32)
  vias: v1(62.48,47.5) v1(62.48,46.23) v1(63.75,47.5) v1(63.75,46.23) v1(74.68,21.59) v1(75.56,20.57)
VIN_MAIN: length 40.8
  TOP w0.381: R21.2 v1(66.04,69.47)
  ART03 w0.762: v1(66.04,69.47) 65.41,70.1 42.42,70.1 39.62,72.9 v1(32.26,72.9) v1(32.26,74.17)
  BOTTOM w0.381: R3.1 37.59,75.44 ; D8.1 65.72,69.15 v1(66.04,69.47)
  BOTTOM w0.508: 39.5,75.18 39.71,75.4 U1.2
  vias: v1(25.91,74.17) v1(25.91,72.9) v1(27.18,74.17) v1(27.18,72.9) v1(30.99,74.17) v1(30.99,72.9)
VIN_MAIN_MONITOR: length 35.7
  TOP w0.152: v1(67.56,38.73) 68.2,38.1 69.09,38.1 R31.1 ; R21.1 66.04,66.67 v1(65.66,66.29)
  ART04 w0.127: v1(67.56,38.73) 65.53,40.77 65.53,49.53 69.6,53.59 69.6,62.36 v1(65.66,66.29)
VIN_SPARE: length 48.7
  TOP w0.381: R22.2 v1(67.31,69.47) ; R10.1 v1(34.92,62.99)
  ART03 w0.762: v1(67.31,69.47) 67.31,68.58 66.42,67.69 64.77,67.69 63.25,66.17 35.69,66.17 32.26,62.74 v1(32.26,60.07) v1(32.26,58.8)
  BOTTOM w0.254: 37.97,61.21 38.23,61.48 U3.4
  BOTTOM w0.381: v1(34.92,62.99) 34.92,61.21 ; D8.2 67.63,69.15 v1(67.31,69.47)
  vias: v1(25.91,60.07) v1(25.91,58.8) v1(27.18,60.07) v1(27.18,58.8) v1(30.99,60.07) v1(30.99,58.8)
VIN_SPARE_MONITOR: length 32
  TOP w0.152: R22.1 67.31,66.67 v1(67.69,66.29) ; v1(67.56,41.27) 68.2,40.64 69.09,40.64 R25.1
  ART04 w0.152: v1(67.69,66.29) 69.98,64.01 69.98,53.34 66.29,49.66 66.29,42.55 v1(67.56,41.27)
A1: length 34.9
  TOP w0.254: v1(15.88,55.24) 15.55,55.57 D20.1 14.67,55.57 13.97,56.26 11.68,56.26 11.5,56.44 J1.37 ; v1(30.48,46.99) U11.12 v1(30.48,49.91) 30.86,50.29 30.86,51.44
  ART03 w0.254: v1(30.48,49.91) 29.84,49.28 26.16,49.28 20.19,55.24 v1(15.88,55.24)
  BOTTOM w0.254: U12.12 v1(30.48,46.99)
A2: length 48.7
  TOP w0.254: v1(40.64,46.99) U13.12 v1(40.64,49.91) 41.02,50.29 R66.1 ; J1.56 8.04,52.82 9.25,51.62 13.9,51.62 14.67,52.39 D22.1 15.55,52.39 v1(15.88,52.07)
  ART03 w0.254: v1(15.88,52.07) 20.32,52.07 26.92,45.47 39.12,45.47 v1(40.64,46.99)
  BOTTOM w0.254: U14.12 v1(40.64,46.99)
A3: length 55.1
  TOP w0.254: v1(50.8,46.99) U15.12 v1(50.8,49.91) 51.18,50.29 51.18,51.44 ; v1(15.88,45.72) 15.55,46.04 D24.1 10.37,46.04 J1.11
  ART03 w0.254: v1(50.8,46.99) 51.18,46.61 51.18,43.69 50.37,42.88 26.47,42.88 23.62,45.72 v1(15.88,45.72)
  BOTTOM w0.254: U16.12 v1(50.8,46.99)
A4: length 40.4
  TOP w0.254: v1(30.48,31.11) U17.12 v1(30.48,34.04) 30.86,34.42 30.86,35.56 ; J1.32 7.38,43.84 9.25,41.96 13.77,41.96 14.67,42.87 D26.1 15.55,42.87 v1(15.88,42.55)
  ART03 w0.254: v1(15.88,42.55) 15.11,41.78 15.11,40.64 16.26,39.5 19.05,39.5 27.43,31.11 v1(30.48,31.11)
  BOTTOM w0.254: U18.12 v1(30.48,31.11)
A5: length 50.5
  TOP w0.254: v1(40.64,31.11) U19.12 v1(40.64,34.04) 41.02,34.42 R85.1 ; J1.51 4.84,40.22 6.71,38.35 8.04,38.35 9.25,37.14 14.02,37.14 14.67,37.79 D28.1 15.55,37.79 v1(15.88,37.47)
  ART03 w0.254: v1(15.88,37.47) 18.8,37.47 26.67,29.59 39.12,29.59 v1(40.64,31.11)
  BOTTOM w0.254: U20.12 v1(40.64,31.11)
A6: length 54.6
  TOP w0.254: v1(15.88,34.29) 15.55,34.61 D30.1 14.67,34.61 13.58,33.52 J1.6 ; 51.18,35.56 51.18,34.42 v1(50.8,34.04) U21.12 v1(50.8,31.11)
  ART03 w0.254: v1(15.88,34.29) 18.92,34.29 26.11,27.1 45.02,27.1 49.03,31.11 v1(50.8,31.11)
  BOTTOM w0.254: U22.12 v1(50.8,31.11)
A7: length 45.1
  TOP w0.254: J1.27 7.38,31.77 9.25,29.9 10.72,29.9 11.43,30.61 13.84,30.61 14.67,31.44 D32.1 15.55,31.44 v1(15.88,31.11) ; 30.86,19.68 30.86,18.54 v1(30.48,18.16) U23.12 v1(30.48,15.24)
  ART03 w0.254: v1(30.48,15.24) 29.72,16 26.16,16 20.32,21.84 20.32,26.8 17.91,29.21 15.62,29.21 15.11,29.72 15.11,30.35 v1(15.88,31.11)
  BOTTOM w0.254: U24.12 v1(30.48,15.24)
A8: length 55.8
  TOP w0.254: J1.46 4.84,28.15 6.71,26.28 8.04,26.28 9.25,25.07 10.72,25.07 13.91,28.26 D34.1 15.55,28.26 v1(15.88,27.94) ; v1(40.64,15.24) U25.12 v1(40.64,18.16) 41.02,18.54 R102.1
  ART03 w0.254: v1(15.88,27.94) 16.26,27.94 19.3,24.89 19.3,21.34 26.42,14.22 39.62,14.22 v1(40.64,15.24)
  BOTTOM w0.254: U26.12 v1(40.64,15.24)
A9: length 58.3
  TOP w0.254: J1.1 11.04,21.45 14.67,25.09 D36.1 15.55,25.09 v1(15.88,24.77) ; 51.18,19.68 51.18,18.54 v1(50.8,18.16) U27.12 v1(50.8,15.24)
  ART03 w0.254: v1(50.8,15.24) 50.19,14.63 44.44,14.63 42.66,12.85 25.5,12.85 16.51,21.84 16.51,24.13 v1(15.88,24.77)
  BOTTOM w0.254: U28.12 v1(50.8,15.24)
A10: length 81.7
  TOP w0.254: v1(111.12,15.24) U47.12 111.12,17.91 111.51,18.29 R170.1
  ART03 w0.254: v1(111.12,15.24) 112.65,13.72 120.46,13.72 121.86,15.11 135.38,15.11 136.5,14 142.14,14 147.02,18.87 147.02,39.04 144.47,41.59 v1(143.51,41.59)
  BOTTOM w0.254: J2.8 147.18,41.59 v1(143.51,41.59) D52.1 ; v1(111.12,15.24) U48.12
A11: length 119.8
  TOP w0.254: R201.2 114.94,40.37 114.94,36.2 116.08,35.05 124.45,35.05 124.89,34.61 124.89,23.2 129.42,18.67 130.18,18.67 v1(130.81,18.03)
  ART03 w0.254: v1(143.51,54.29) 144.34,54.29 148.39,50.24 148.39,17.96 141.35,10.92 132.31,10.92 131.29,9.91 v1(130.81,9.91)
  ART04 w0.254: v1(130.81,9.91) 131.44,10.54 131.44,17.4 v1(130.81,18.03)
  BOTTOM w0.254: R208.2 131.06,10.16 v1(130.81,9.91) ; D53.1 v1(143.51,54.29) 146.87,54.29 148.51,55.92 J2.3
A_SWITCH: length 37
  TOP w0.254: J2.42 153.9,34.08 153.9,29.18 150.43,25.71 D17.1 v1(144.15,25.71) ; U7.12 v1(135.89,18.03)
  ART03 w0.254: v1(144.15,25.71) 143.51,25.08 143.51,19.43 140.56,16.48 137.92,16.48 136.37,18.03 v1(135.89,18.03)
  BOTTOM w0.254: v1(135.89,18.03) 136.4,17.53 R45.1
B1: length 37.1
  TOP w0.254: J1.36 11.36,54.03 11.81,54.48 13.84,54.48 14.67,53.65 D20.2 15.55,53.65 v1(15.88,53.98) ; R60.2 33.66,51.38 32.38,50.11 32.38,49.66 31.75,49.02 U11.11 v1(31.75,46.99)
  ART03 w0.254: v1(31.75,46.99) 30.99,47.75 26.92,47.75 20.7,53.98 v1(15.88,53.98)
  BOTTOM w0.254: U12.11 v1(31.75,46.99)
B2: length 50.6
  TOP w0.254: v1(41.91,46.99) U13.11 41.91,49.02 42.55,49.66 42.55,50.07 43.81,51.34 R66.2 ; v1(15.88,50.8) 15.55,50.48 D22.2 14.67,50.48 14.1,49.91 11.43,49.91 10.72,49.2 9.25,49.2 8.04,50.41 J1.55
  ART03 w0.254: v1(15.88,50.8) 20.83,50.8 26.62,45.01 39.93,45.01 v1(41.91,46.99)
  BOTTOM w0.254: U14.11 v1(41.91,46.99)
B3: length 56.4
  TOP w0.254: J1.10 10.87,44.13 D24.2 15.55,44.13 v1(15.88,44.45) ; v1(52.07,46.99) U15.11 52.07,49.02 52.7,49.66 52.7,50.07 53.98,51.34 R72.2
  ART03 w0.254: v1(15.88,44.45) 24.13,44.45 26.16,42.42 50.67,42.42 51.69,43.43 51.69,46.61 v1(52.07,46.99)
  BOTTOM w0.254: U16.11 v1(52.07,46.99)
B4: length 39.8
  TOP w0.254: J1.31 7.38,41.43 9.25,39.55 13.26,39.55 14.67,40.95 D26.2 15.55,40.95 v1(15.88,41.27) ; R80.2 33.66,35.46 32.38,34.19 32.38,33.78 31.75,33.15 U17.11 v1(31.75,31.11)
  ART03 w0.254: v1(31.75,31.11) 31.19,31.67 27.64,31.67 18.87,40.44 16.71,40.44 v1(15.88,41.27)
  BOTTOM w0.254: U18.11 v1(31.75,31.11)
B5: length 52.4
  TOP w0.254: J1.50 4.84,37.81 6.71,35.93 8.04,35.93 9.25,34.73 10.34,34.73 10.92,35.31 14.1,35.31 14.67,35.87 D28.2 15.55,35.87 v1(15.88,36.2) ; R85.2 43.81,35.46 42.55,34.19 42.55,33.78 41.91,33.15 U19.11 v1(41.91,31.11)
  ART03 w0.254: v1(41.91,31.11) 39.93,29.13 26.37,29.13 19.3,36.2 v1(15.88,36.2)
  BOTTOM w0.254: U20.11 v1(41.91,31.11)
B6: length 56.6
  TOP w0.254: v1(52.07,31.11) U21.11 52.07,33.15 52.7,33.78 52.7,34.19 53.98,35.46 R91.2 ; J1.5 10.94,32.13 14.1,32.13 14.67,32.7 D30.2 15.55,32.7 v1(15.88,33.02)
  ART03 w0.254: v1(52.07,31.11) 51.44,30.48 49.05,30.48 45.21,26.64 25.81,26.64 19.43,33.02 v1(15.88,33.02)
  BOTTOM w0.254: U22.11 v1(52.07,31.11)
B7: length 44.7
  TOP w0.254: J1.26 7.38,29.36 9.18,27.56 11.18,27.56 12.57,28.96 14.1,28.96 14.67,29.52 D32.2 15.55,29.52 v1(15.88,29.84) ; v1(31.75,15.24) U23.11 31.75,17.27 32.38,17.91 32.38,18.32 33.66,19.59 R96.2
  ART03 w0.254: v1(31.75,15.24) 30.48,16.51 26.42,16.51 20.83,22.1 20.83,27.05 18.03,29.84 v1(15.88,29.84)
  BOTTOM w0.254: U24.11 v1(31.75,15.24)
B8: length 57.8
  TOP w0.254: v1(15.88,26.67) 15.55,26.35 D34.2 14.16,26.35 10.47,22.66 9.25,22.66 8.04,23.87 6.71,23.87 4.84,25.74 J1.45 ; R102.2 43.81,19.59 42.55,18.32 42.55,17.91 41.91,17.27 U25.11 v1(41.91,15.24)
  ART03 w0.254: v1(41.91,15.24) 40.44,13.77 26.11,13.77 18.8,21.08 18.8,24.64 16.76,26.67 v1(15.88,26.67)
  BOTTOM w0.254: U26.11 v1(41.91,15.24)
B9: length 63.4
  TOP w0.254: R109.2 53.98,19.56 52.7,18.29 52.7,17.91 52.07,17.27 U27.11 v1(52.07,15.24) ; v1(15.88,23.5) 15.55,23.17 D36.2 14.67,23.17 11.81,20.32 8.96,20.32 7.38,21.91 J1.23
  ART03 w0.254: v1(52.07,15.24) 51.47,14.64 50.93,14.64 50.46,14.17 44.63,14.17 42.85,12.4 25.2,12.4 15.88,21.72 v1(15.88,23.5)
  BOTTOM w0.254: U28.11 v1(52.07,15.24)
B10: length 82
  TOP w0.254: v1(112.39,15.24) U47.11 112.39,17.14 113.03,17.78 113.03,18.19 114.3,19.46 R170.2
  ART03 w0.254: v1(143.51,43.5) 142.88,42.87 142.88,41.27 143.13,41.02 143.89,41.02 144.78,40.13 144.78,38.61 145.82,37.57 145.82,25.88 146.18,25.53 146.18,18.8 141.83,14.45 136.8,14.45 135.64,15.62 121.72,15.62 120.27,14.17 113.46,14.17 v1(112.39,15.24)
  BOTTOM w0.254: J2.7 146.81,43.5 v1(143.51,43.5) D52.2 ; U48.11 v1(112.39,15.24)
B11: length 109.6
  TOP w0.254: R194.2 109.58,27.44 115.38,21.64 125.16,21.64 128.27,18.53 v1(128.27,18.03) ; v1(132.08,9.91) 132.08,10.05 R209.2
  ART03 w0.254: v1(143.51,56.2) 148.84,50.87 148.84,17.65 141.66,10.46 132.64,10.46 v1(132.08,9.91)
  ART04 w0.254: v1(132.08,9.91) 131.44,9.27 128.02,9.27 127.64,9.65 127.64,17.4 v1(128.27,18.03)
  BOTTOM w0.254: J2.2 147.62,58.21 145.61,56.2 v1(143.51,56.2) D53.2
B_SWITCH: length 35.7
  TOP w0.254: v1(144.15,27.63) D17.2 148.4,27.63 148.72,27.3 150.62,27.3 151.38,28.07 151.38,32.96 J2.28 ; U7.11 v1(137.16,18.03)
  ART03 w0.254: v1(144.15,27.63) 143,26.48 143,19.68 140.26,16.94 138.25,16.94 v1(137.16,18.03)
  BOTTOM w0.254: R45.2 139.19,17.65 139.06,17.78 139.06,18.29 138.68,18.67 137.79,18.67 v1(137.16,18.03)
BOARD_ID0: length 4.3
  TOP w0.152: U6.25 80.26,34.17 v1(80.39,34.04) R158.1
  BOTTOM w0.152: v1(80.39,34.04) R158.1
BOARD_ID1: length 4.7
  TOP w0.152: U6.26 80.76,34.94 v1(81.66,34.04) R160.1
  BOTTOM w0.152: R160.1 v1(81.66,34.04)
BOARD_ID2: length 5.3
  TOP w0.152: U6.27 81.26,35.2 82.42,34.04 v1(82.93,34.04) R162.1
  BOTTOM w0.152: v1(82.93,34.04) R162.1
BOARD_ID3: length 6
  TOP w0.152: U6.28 81.76,35.33 82.55,34.54 83.69,34.54 v1(84.2,34.04) R164.1
  BOTTOM w0.152: R164.1 v1(84.2,34.04)
CON_MAIN_USB_N: length 25.6
  TOP w0.15: v1(19.16,70.48) 19.55,70.1 19.55,69.9 19.28,69.64 L8.1 ; v1(15.75,69.85) 15.43,70.16 U44.1 13.4,70.16 12.57,69.34 12.19,69.34 11.81,69.72 11.81,70.74 11.05,71.5 7.99,71.5 5.97,69.48 5.97,66.29 5.65,65.98 5.14,65.98 4.84,66.28 J1.62
  ART04 w0.13: v1(19.16,70.48) 19.52,70.13 19.52,69.18 18.92,68.58 17.53,68.58 16.72,69.38 16.22,69.38 v1(15.75,69.85)
CON_MAIN_USB_P: length 25.6
  TOP w0.15: J1.61 4.84,65.35 5.19,65.7 5.77,65.7 6.25,66.18 6.25,69.36 8.11,71.22 10.93,71.22 11.53,70.62 11.53,69.61 12.08,69.07 12.57,69.07 13.37,68.27 U44.3 15.43,68.27 v1(15.75,68.58) ; L8.4 20.09,69.64 19.82,69.9 19.82,70.1 v1(20.21,70.48)
  ART04 w0.13: v1(20.21,70.48) 19.85,70.13 19.85,69.04 19.06,68.25 17.39,68.25 16.59,69.05 16.22,69.05 v1(15.75,68.58)
CON_MAIN_VBUS: length 62.9
  TOP w0.508: U44.5 v1(18.16,69.22)
  ART03 w0.508: J1.60 3.3,64.01 3.3,68.96 5.97,71.63 15.75,71.63 v1(18.16,69.22) 41.78,69.22 41.91,69.09 v1(54.61,69.09) v1(55.88,69.09)
CON_SPARE_USB_N: length 11.9
  TOP w0.15: v1(144.27,29.84) 144.59,29.53 U46.1 146.37,29.53 147.19,30.35 147.56,30.35 148.42,29.49 149.7,29.49 150.09,29.11 J2.15
  BOTTOM w0.15: L9.1 142.77,28.17 142.51,28.44 142.51,29.6 143.24,30.34 143.78,30.34 v1(144.27,29.84)
CON_SPARE_USB_P: length 12
  TOP w0.15: v1(144.27,31.11) 144.59,31.43 U46.3 146.39,31.43 147.19,30.63 147.68,30.63 148.54,29.77 149.08,29.77 J2.14
  BOTTOM w0.15: L9.4 141.97,28.17 142.23,28.44 142.23,29.72 143.13,30.62 143.78,30.62 v1(144.27,31.11)
CON_SPARE_VBUS: length 63.2
  TOP w0.508: J2.13 147.62,33.06 146.94,32.38 141.99,32.38 141.48,31.88 v1(141.48,30.48) ; v1(106.55,18.41) 106.55,16.13 109.09,13.59 126.24,13.59 129.16,16.51 131.7,16.51 132.58,17.39 132.58,18.53 133.35,19.3 139.45,19.3 141.48,21.34 v1(141.48,30.48) ; v1(141.48,30.48) U46.5
  vias: v1(106.55,19.68)
ISO_A12: length 40.9
  TOP w0.254: R124.1 135.76,29.97 v1(133.99,31.75) U33.18 ; v1(141.35,43.5) D42.1 142.56,43.5 143.13,44.07 147.45,44.07 149.01,45.64 J2.23
  ART03 w0.254: v1(133.99,31.75) 134.62,31.11 134.62,26.04 v1(133.99,25.4)
  ART04 w0.254: v1(141.35,43.5) 140.14,42.29 137.67,42.29 135.13,39.75 135.13,32.89 v1(133.99,31.75)
  BOTTOM w0.254: U34.18 v1(133.99,25.4)
ISO_A13: length 45.6
  TOP w0.254: R129.1 135.76,73.79 v1(133.99,75.56) U36.18 ; v1(141.35,62.55) D44.1 150.09,62.55 152.14,60.49 153.37,60.49 153.9,59.97 153.9,58.34 J2.18
  ART03 w0.254: v1(133.99,69.22) 134.62,69.85 134.62,74.93 v1(133.99,75.56)
  ART04 w0.254: v1(133.99,75.56) 135.51,74.04 135.51,73.66 141.35,67.82 v1(141.35,62.55)
  BOTTOM w0.254: U35.18 v1(133.99,69.22)
ISO_A14: length 43.3
  TOP w0.254: R134.1 135.76,44.58 v1(133.99,46.35) U37.18 ; v1(141.35,49.85) D46.1 148.4,49.85 148.76,50.21 150.78,50.21 151.93,51.35 153.32,51.35 154.47,50.21 155.79,50.21 156.34,49.66 156.34,45.66 J2.38
  ART03 w0.254: v1(133.99,46.35) 134.62,45.72 134.62,40.64 v1(133.99,40.01)
  ART04 w0.254: v1(133.99,46.35) 134.62,46.99 138.49,46.99 v1(141.35,49.85)
  BOTTOM w0.254: U38.18 v1(133.99,40.01)
ISO_A15: length 36.7
  TOP w0.254: v1(141.35,56.2) D48.1 142.56,56.2 143.43,57.07 150.71,57.07 151.85,55.92 J2.33 ; U39.18 v1(133.99,60.96) 135.76,59.18 R139.1
  ART03 w0.254: v1(133.99,54.61) 134.62,55.24 134.62,60.33 v1(133.99,60.96)
  ART04 w0.254: v1(133.99,60.96) 135.38,59.56 135.38,59.18 138.36,56.2 v1(141.35,56.2)
  BOTTOM w0.254: U40.18 v1(133.99,54.61)
ISO_B12: length 45.5
  TOP w0.254: U33.17 v1(133.99,30.48) 134.62,29.84 134.62,28.19 135.64,27.18 R124.2 ; v1(141.35,41.59) D42.2 142.56,41.59 143.13,41.02 146.43,41.02 148.76,43.35 150.78,43.35 151.93,44.49 153.32,44.49 153.9,45.06 153.9,46.65 J2.22
  ART04 w0.254: v1(133.99,30.48) 135.64,32.13 135.64,39.37 137.86,41.59 v1(141.35,41.59)
  BOTTOM w0.254: v1(133.99,30.48) 134.62,29.84 134.62,27.43 133.86,26.67 U34.17
ISO_B13: length 40
  TOP w0.254: U36.17 v1(133.99,74.3) 134.62,73.66 134.62,72.01 135.64,70.99 R129.2 ; v1(141.35,60.64) D44.2 146.75,60.64 148.03,59.35 J2.17
  ART04 w0.254: v1(133.99,74.3) 140.59,67.69 140.59,61.4 v1(141.35,60.64)
  BOTTOM w0.254: U35.17 133.86,70.48 134.62,71.25 134.62,73.66 v1(133.99,74.3)
ISO_B14: length 35.5
  TOP w0.254: v1(141.35,47.94) D46.2 150.81,47.94 151.93,49.06 153.32,49.06 155.17,47.22 J2.37 ; R134.2 135.64,41.78 134.62,42.8 134.62,44.45 v1(133.99,45.09) U37.17
  ART04 w0.254: v1(141.35,47.94) 139.13,45.72 134.62,45.72 v1(133.99,45.09)
  BOTTOM w0.254: v1(133.99,45.09) 134.62,44.45 134.62,42.04 133.86,41.27 U38.17
ISO_B15: length 41.5
  TOP w0.254: U39.17 v1(133.99,59.69) 134.62,59.05 134.62,57.4 135.64,56.39 R139.2 ; v1(141.35,54.29) D48.2 142.69,54.29 143.26,53.72 146.69,53.72 147.74,54.78 150.71,54.78 151.85,53.64 153.08,53.64 154.22,54.78 155.87,54.78 156.46,55.37 156.46,56.91 J2.32
  ART04 w0.254: v1(141.35,54.29) 140.27,55.37 138.3,55.37 v1(133.99,59.69)
  BOTTOM w0.254: U40.17 133.86,55.88 134.62,56.64 134.62,59.05 v1(133.99,59.69)
ISO_Y12: length 41.6
  TOP w0.254: U33.13 v1(130.94,25.4)
  ART04 w0.254: v1(130.94,25.4) 131.32,25.4 136.65,30.73 136.65,35.81 139.25,38.41 v1(141.35,38.41)
  BOTTOM w0.254: J2.25 152.63,40.62 150.78,38.78 148.76,38.78 147.83,37.85 143.13,37.85 142.56,38.41 D41.1 v1(141.35,38.41) ; U34.13 131.32,31.75 130.3,30.73 130.3,26.04 v1(130.94,25.4)
ISO_Y13: length 44.8
  TOP w0.254: U36.13 v1(130.94,69.22)
  ART04 w0.254: v1(130.94,69.22) 132.72,69.22 139.32,62.61 139.32,59.5 v1(141.35,57.46)
  BOTTOM w0.254: U35.13 131.19,75.56 130.3,74.68 130.3,69.85 v1(130.94,69.22) ; v1(141.35,57.46) D43.1 145.98,57.46 147.83,59.31 151,59.31 151.36,58.96 151.36,54.56 152.63,53.29 J2.20
ISO_Y14: length 43.3
  TOP w0.254: U37.13 v1(130.94,40.01)
  ART04 w0.254: v1(130.94,40.01) 133.86,42.93 139.51,42.93 v1(141.35,44.76)
  BOTTOM w0.254: v1(130.94,40.01) 130.3,40.64 130.3,45.34 131.32,46.35 U38.13 ; J2.40 153.9,41.19 153.9,43.92 153.32,44.49 151.93,44.49 151.38,45.04 151.38,46.97 150.48,47.88 148.84,47.88 145.73,44.76 D45.1 v1(141.35,44.76)
ISO_Y15: length 40
  TOP w0.254: U39.13 v1(130.94,54.61)
  ART04 w0.254: v1(141.35,51.11) 134.43,51.11 v1(130.94,54.61)
  BOTTOM w0.254: v1(141.35,51.11) D47.1 143.03,50.55 147.07,50.55 149.01,52.49 150.43,52.49 151.36,51.57 151.36,49.99 152.28,49.06 153.32,49.06 155.17,50.91 J2.35 ; v1(130.94,54.61) 130.3,55.24 130.3,59.94 131.32,60.96 U40.13
ISO_Z12: length 33.3
  TOP w0.254: U33.15 133.73,27.94 133.99,28.19 v1(133.99,29.21)
  ART04 w0.254: v1(133.99,29.21) 136.14,31.37 136.14,38.86 136.65,39.37 140.4,39.37 v1(141.35,40.33)
  BOTTOM w0.254: J2.24 152.63,42.9 150.78,41.06 149.27,41.06 149.1,40.89 143.13,40.89 142.56,40.33 D41.2 v1(141.35,40.33) ; U34.15 v1(133.99,29.21)
ISO_Z13: length 40.9
  TOP w0.254: v1(133.99,73.03) 133.99,72.01 133.73,71.75 U36.15
  ART04 w0.254: v1(133.99,73.03) 136.14,70.87 136.14,66.8 139.95,62.99 139.95,60.77 v1(141.35,59.38)
  BOTTOM w0.254: U35.15 v1(133.99,73.03) ; v1(141.35,59.38) D43.2 145.23,59.38 147.83,61.98 150.62,61.98 152.02,60.58 153.16,60.58 153.92,59.82 153.92,56.08 J2.19
ISO_Z14: length 35.5
  TOP w0.254: U37.15 133.73,42.55 133.99,42.8 v1(133.99,43.81)
  ART04 w0.254: v1(141.35,46.68) 139.13,44.45 134.62,44.45 v1(133.99,43.81)
  BOTTOM w0.254: J2.39 156.34,43.38 156.34,45.09 155.79,45.64 154.47,45.64 153.32,46.78 152.22,46.78 151.36,47.65 151.36,49.29 150.48,50.16 148.84,50.16 145.35,46.68 D45.2 v1(141.35,46.68) ; U38.15 v1(133.99,43.81)
ISO_Z15: length 33.7
  TOP w0.254: U39.15 133.73,57.15 133.99,57.4 v1(133.99,58.42)
  ART04 w0.254: v1(133.99,58.42) 133.99,55.63 136.91,52.7 141.03,52.7 v1(141.35,53.03)
  BOTTOM w0.254: U40.15 v1(133.99,58.42) ; J2.34 155.17,53.19 153.32,51.35 152.28,51.35 151.36,52.27 151.36,53.86 150.48,54.74 148.46,54.74 147.32,53.59 143.26,53.59 142.69,53.03 D47.2 v1(141.35,53.03)
MAIN_ID2: length 102.3
  TOP w0.152: v1(87.12,40.26) 86.78,39.91 U6.36
  ART03 w0.127: J3.12 35,87 35,85.4 36.7,83.69 59.82,83.69 64.64,78.87 87.76,78.87 v1(88.39,79.5)
  ART04 w0.127: v1(88.39,79.5) 88.39,47.88 88.9,47.37 88.9,45.34 87.76,44.2 87.76,40.89 v1(87.12,40.26)
  BOTTOM w0.152: R39.2 87,40.39 v1(87.12,40.26)
MAIN_POWER_EN: length 54.6
  TOP w0.152: v1(81.92,58.67) 81.53,58.29 Q1.3
  ART03 w0.127: v1(39.5,76.33) 44.83,70.99 66.8,70.99 75.56,62.23 79.76,62.23 80.14,61.85 80.14,60.45 v1(81.92,58.67)
  BOTTOM w0.152: R3.2 v1(39.5,76.33) 39.62,76.2 U1.3
MAIN_SAFE_MODE_EN_N: length 336.1
  TOP w0.152: U13.4 v1(41.91,41.53) ; v1(53.34,9.78) 52.45,9.78 52.07,10.16 U27.4 ; U15.4 v1(52.07,41.53) ; U21.4 v1(52.07,25.65) ; U39.6 v1(124.33,57.15) ; U23.4 v1(31.75,9.78) ; U19.4 v1(41.91,25.65) ; U47.4 v1(112.39,9.91) ; U17.4 v1(31.75,25.65) ; U49.4 v1(123.19,9.91) ; U11.4 v1(31.75,41.53) ; U33.6 v1(124.33,27.94) ; U25.4 v1(41.91,9.78) ; U37.6 v1(124.33,42.55)
  ART03 w0.127: v1(52.07,41.53) 51.57,42.02 42.41,42.02 v1(41.91,41.53) ; v1(53.34,9.78) 53.85,10.29 58.8,10.29 60.33,11.81 72.52,11.81 73.53,12.83 94.08,12.83 97.03,9.88 107.72,9.88 108.46,9.14 111.63,9.14 v1(112.39,9.91) 112.9,10.41 117.35,10.41 118.75,9.02 122.3,9.02 v1(123.19,9.91)
  ART04 w0.127: v1(124.33,73.03) 123.32,72.01 123.32,58.17 v1(124.33,57.15) 123.32,56.13 123.32,43.56 v1(124.33,42.55) 123.32,41.53 123.32,28.96 v1(124.33,27.94) 124.97,27.3 124.97,21.46 122.56,19.05 122.56,10.54 v1(123.19,9.91) ; v1(52.07,41.53) 52.7,40.89 52.7,26.29 v1(52.07,25.65) 52.7,25.02 52.7,10.41 v1(53.34,9.78) ; v1(41.91,41.53) 42.55,40.89 42.55,26.29 v1(41.91,25.65) 42.55,25.02 42.55,10.41 v1(41.91,9.78) 40.77,9.78 40.13,10.41 32.77,10.41 32.13,9.78 v1(31.75,9.78) 31.75,13.97 32.38,14.61 32.38,25.02 v1(31.75,25.65) 32.38,26.29 32.38,40.89 v1(31.75,41.53) 32.38,42.16 32.38,52.58 33.15,53.34 33.15,76.58 36.07,79.5 37.08,79.5 v1(38.61,81.03)
  BOTTOM w0.152: R1.2 v1(38.61,81.03) 38.61,84.71 39,85.1 39,87 J3.16 ; U35.6 v1(124.33,73.03)
MAIN_UART_RX0_DEBUG: length 68.7
  ART03 w0.127: v1(85.85,79.5) 64.64,79.5 60.07,84.07 43.93,84.07 J3.19
  BOTTOM w0.152: v1(85.85,79.5) 86.49,78.87 86.49,60.83 85.98,60.33 R145.1
MAIN_UART_RX1: length 65.3
  TOP w0.152: R62.1 R61.1 v1(29.21,38.61)
  ART04 w0.127: v1(29.21,38.61) 30.35,39.75 30.35,42.55 28.57,44.32 28.57,81.15 31.37,83.95 43.95,83.95 J3.23
MAIN_UART_RX2: length 56.5
  TOP w0.152: R67.1 R68.1 v1(39.37,38.61)
  ART04 w0.127: v1(39.37,38.61) 38.73,39.24 38.73,56.01 47.88,65.15 47.88,81.66 v1(48.39,82.17)
  BOTTOM w0.152: v1(48.39,82.17) 49,82.78 49,87 J3.26
MAIN_UART_RX3: length 57.6
  TOP w0.152: v1(49.53,38.61) R74.1 R73.1
  ART04 w0.127: v1(55.5,82.17) 54.99,81.66 54.99,72.01 51.94,68.96 51.94,59.31 48.9,56.26 48.9,39.24 v1(49.53,38.61)
  BOTTOM w0.152: v1(55.5,82.17) 54.61,83.06 53.21,83.06 51,85.27 51,87 J3.28
MAIN_UART_RX4: length 93.2
  TOP w0.152: R78.1 R79.1 v1(29.21,22.73)
  ART04 w0.127: v1(29.21,22.73) R79.1 30.23,24.64 30.23,26.74 28.57,28.39 28.57,38.73 29.97,40.13 29.97,42.35 27.3,45.01 27.3,52.96 28.19,53.85 28.19,81.31 31.21,84.33 42.04,84.33 43,85.29 43,88.47 43.56,89.03 50.97,89.03 J3.30
MAIN_UART_RX5: length 74.8
  TOP w0.152: R86.1 R84.1 v1(39.37,22.73)
  ART04 w0.127: v1(39.37,22.73) 37.47,24.64 37.47,55.24 47.5,65.28 47.5,82.42 48.51,83.44 51.44,83.44 J3.31
MAIN_UART_RX6: length 72.5
  TOP w0.152: v1(49.53,22.73) R90.1 R92.1
  ART04 w0.127: J3.34 57,87 57,85.32 54.63,82.95 54.63,72.16 51.58,69.11 51.58,59.46 47.62,55.5 47.62,36.58 48.9,35.31 48.9,23.37 v1(49.53,22.73)
MAIN_UART_RX7: length 114.4
  TOP w0.152: R97.1 R98.1 v1(29.21,6.86)
  ART04 w0.127: J3.38 61,87 62.48,87 62.99,86.49 62.99,85.22 60.98,83.21 60.98,72.29 59.44,70.74 59.44,58.04 57.28,55.88 57.28,9.4 55.75,7.87 30.23,7.87 v1(29.21,6.86)
MAIN_UART_RX8: length 103.1
  TOP w0.152: R103.1 R104.1 v1(39.37,6.86)
  ART04 w0.127: J3.40 63.37,86.63 63.37,84.96 61.34,82.93 61.34,72.14 59.82,70.61 59.82,57.91 57.66,55.75 57.66,9.27 55.88,7.49 40.01,7.49 v1(39.37,6.86)
MAIN_UART_RX9: length 22.1
  TOP w0.152: J4.8 30.59,5.59 46.1,5.59 R110.1 R108.1
MAIN_UART_RX10: length 90.6
  TOP w0.152: v1(108.58,6.73) R165.1 R169.1
  ART03 w0.127: v1(60.33,6.86) 60.58,6.86 64.01,10.29 73.15,10.29 74.17,11.3 93.73,11.3 97.54,7.49 107.31,7.49 108.07,6.73 v1(108.58,6.73)
  BOTTOM w0.152: J4.9 29.97,3.03 29.97,4.7 31.5,6.22 56.39,6.22 58.8,8.64 59.44,8.64 59.82,8.26 59.82,7.37 v1(60.33,6.86)
MAIN_UART_RX11: length 97.6
  TOP w0.152: v1(119.38,6.73) R176.1 R174.1
  ART03 w0.127: v1(119.38,6.73) 118.75,7.37 107.9,7.37 107.39,7.87 97.63,7.87 93.82,11.68 74.01,11.68 72.99,10.67 63.85,10.67 60.55,7.37 59.69,7.37 v1(59.18,6.86)
  BOTTOM w0.152: J4.11 32,3 32,4.57 32.89,5.46 57.78,5.46 v1(59.18,6.86)
